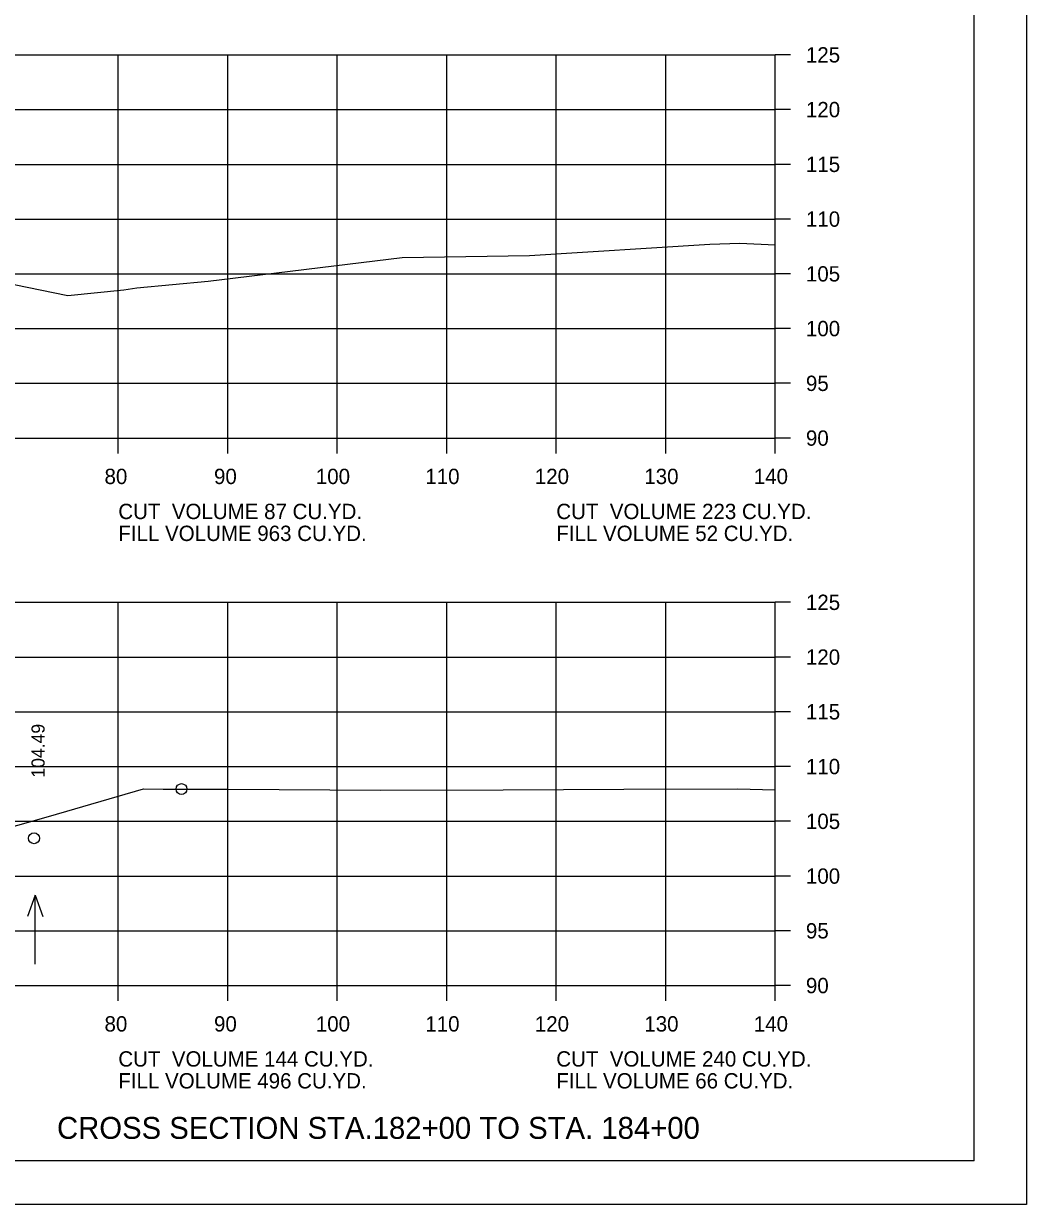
# Model space of a CAD drawing. Extents: x 1175611 to 1176402, y -433344 to -416213.
# Drawn here: x 1175852.3 to 1175943.9, y -426730.1 to -426622.2 of the extents above; entities that cross this region are included whole.
import ezdxf

# ---------------------------------------------------------------- set-up
doc = ezdxf.new("R2010")
doc.units = 0
for name, color, linetype in [('Default', 7, 'Continuous'), ('R_Axis', 7, 'Continuous'), ('R_Axis Annot', 7, 'Continuous'), ('R_Border', 7, 'Continuous'), ('R_Draft', 7, 'Continuous'), ('R_Exist Surface', 7, 'Continuous'), ('R_Grid', 7, 'Continuous'), ('R_No Plot', 7, 'Continuous'), ('R_Water Annot', 7, 'Continuous'), ('R_Xsect Elev', 7, 'Continuous')]:
    doc.layers.add(name, color=color, linetype=linetype)

msp = doc.modelspace()

# ---------------------------------------------------------------- linework, layer by layer
at = {"layer": 'R_Axis'}
for p, q in [((1175920.97, -426660.07), (1175920.97, -426625.07)), ((1175922.37, -426625.07), (1175920.97, -426625.07)), ((1175922.37, -426630.07), (1175920.97, -426630.07)), ((1175922.37, -426635.07), (1175920.97, -426635.07)), ((1175922.37, -426640.07), (1175920.97, -426640.07)), ((1175922.37, -426645.07), (1175920.97, -426645.07)), ((1175922.37, -426650.07), (1175920.97, -426650.07)), ((1175922.37, -426655.07), (1175920.97, -426655.07)), ((1175640.97, -426660.07), (1175920.97, -426660.07)), ((1175860.97, -426661.47), (1175860.97, -426660.07)), ((1175870.97, -426661.47), (1175870.97, -426660.07)), ((1175880.97, -426661.47), (1175880.97, -426660.07)), ((1175890.97, -426661.47), (1175890.97, -426660.07)), ((1175900.97, -426661.47), (1175900.97, -426660.07)), ((1175910.97, -426661.47), (1175910.97, -426660.07)), ((1175920.97, -426661.47), (1175920.97, -426660.07)), ((1175922.37, -426660.07), (1175920.97, -426660.07)), ((1175920.97, -426710.07), (1175920.97, -426675.07)), ((1175922.37, -426675.07), (1175920.97, -426675.07)), ((1175922.37, -426680.07), (1175920.97, -426680.07)), ((1175922.37, -426685.07), (1175920.97, -426685.07)), ((1175922.37, -426690.07), (1175920.97, -426690.07)), ((1175922.37, -426695.07), (1175920.97, -426695.07)), ((1175922.37, -426700.07), (1175920.97, -426700.07)), ((1175922.37, -426705.07), (1175920.97, -426705.07)), ((1175640.97, -426710.07), (1175920.97, -426710.07)), ((1175860.97, -426711.47), (1175860.97, -426710.07)), ((1175870.97, -426711.47), (1175870.97, -426710.07)), ((1175880.97, -426711.47), (1175880.97, -426710.07)), ((1175890.97, -426711.47), (1175890.97, -426710.07)), ((1175900.97, -426711.47), (1175900.97, -426710.07)), ((1175910.97, -426711.47), (1175910.97, -426710.07)), ((1175920.97, -426711.47), (1175920.97, -426710.07)), ((1175922.37, -426710.07), (1175920.97, -426710.07))]:
    msp.add_line(p, q, dxfattribs=at)
at = {"layer": 'R_Border'}
for q in [(1175939.15, -426520.61), (1175622.97, -426726.07)]:
    msp.add_line((1175939.15, -426726.07), q, dxfattribs=at)
at = {"layer": 'R_Exist Surface'}
for points in [[(1175846.69, -426645.08), (1175856.36, -426647.06), (1175861.47, -426646.53), (1175862.65, -426646.35), (1175869.17, -426645.75), (1175886.88, -426643.57), (1175898.51, -426643.4), (1175915, -426642.36), (1175917.73, -426642.28), (1175920.97, -426642.42)], [(1175850.39, -426695.82), (1175854.58, -426694.63), (1175863.27, -426692.09), (1175865.08, -426692.13), (1175870.99, -426692.14), (1175884.95, -426692.24), (1175896.13, -426692.19), (1175907.13, -426692.13), (1175917.52, -426692.11), (1175920.97, -426692.21)]]:
    msp.add_lwpolyline(points, dxfattribs=at)
at = {"layer": 'R_Grid'}
for p, q in [((1175640.97, -426625.07), (1175920.97, -426625.07)), ((1175860.97, -426660.07), (1175860.97, -426625.07)), ((1175870.97, -426660.07), (1175870.97, -426625.07)), ((1175880.97, -426660.07), (1175880.97, -426625.07)), ((1175890.97, -426660.07), (1175890.97, -426625.07)), ((1175900.97, -426660.07), (1175900.97, -426625.07)), ((1175910.97, -426660.07), (1175910.97, -426625.07)), ((1175920.97, -426660.07), (1175920.97, -426625.07)), ((1175640.97, -426630.07), (1175920.97, -426630.07)), ((1175640.97, -426635.07), (1175920.97, -426635.07)), ((1175640.97, -426640.07), (1175920.97, -426640.07)), ((1175640.97, -426645.07), (1175920.97, -426645.07)), ((1175640.97, -426650.07), (1175920.97, -426650.07)), ((1175640.97, -426655.07), (1175920.97, -426655.07)), ((1175640.97, -426660.07), (1175920.97, -426660.07)), ((1175640.97, -426675.07), (1175920.97, -426675.07)), ((1175860.97, -426710.07), (1175860.97, -426675.07)), ((1175870.97, -426710.07), (1175870.97, -426675.07)), ((1175880.97, -426710.07), (1175880.97, -426675.07)), ((1175890.97, -426710.07), (1175890.97, -426675.07)), ((1175900.97, -426710.07), (1175900.97, -426675.07)), ((1175910.97, -426710.07), (1175910.97, -426675.07)), ((1175920.97, -426710.07), (1175920.97, -426675.07)), ((1175640.97, -426680.07), (1175920.97, -426680.07)), ((1175640.97, -426685.07), (1175920.97, -426685.07)), ((1175640.97, -426690.07), (1175920.97, -426690.07)), ((1175640.97, -426695.07), (1175920.97, -426695.07)), ((1175640.97, -426700.07), (1175920.97, -426700.07)), ((1175640.97, -426705.07), (1175920.97, -426705.07)), ((1175640.97, -426710.07), (1175920.97, -426710.07))]:
    msp.add_line(p, q, dxfattribs=at)
at = {"layer": 'R_No Plot'}
msp.add_line((1175610.57, -426730.05), (1175943.91, -426730.05), dxfattribs=at)
msp.add_lwpolyline([(1175610.57, -426516.72), (1175943.91, -426516.72), (1175943.91, -426730.06), (1175610.57, -426730.06)], close=True, dxfattribs=at)
for centre in [(1175866.74, -426692.13), (1175853.27, -426696.62)]:
    msp.add_circle(centre, 0.5, dxfattribs=at)
at = {"layer": 'R_Water Annot'}
for p, q in [((1175853.37, -426701.82), (1175852.67, -426703.75)), ((1175853.37, -426708.11), (1175853.37, -426701.82)), ((1175853.37, -426701.82), (1175854.07, -426703.75))]:
    msp.add_line(p, q, dxfattribs=at)

# ---------------------------------------------------------------- texts
at = {"layer": 'Default'}
for s, p in [('CUT  VOLUME 87 CU.YD.', (1175860.97, -426667.47)), ('CUT  VOLUME 223 CU.YD.', (1175900.97, -426667.47)), ('FILL VOLUME 963 CU.YD.', (1175860.97, -426669.47)), ('FILL VOLUME 52 CU.YD.', (1175900.97, -426669.47)), ('CUT  VOLUME 144 CU.YD.', (1175860.97, -426717.47)), ('CUT  VOLUME 240 CU.YD.', (1175900.97, -426717.47)), ('FILL VOLUME 496 CU.YD.', (1175860.97, -426719.47)), ('FILL VOLUME 66 CU.YD.', (1175900.97, -426719.47))]:
    msp.add_text(s, height=1.4, dxfattribs=at).set_placement(p)
at = {"layer": 'R_Axis Annot'}
for s, p in [('125', (1175923.77, -426625.77)), ('120', (1175923.77, -426630.77)), ('115', (1175923.77, -426635.77)), ('110', (1175923.77, -426640.77)), ('105', (1175923.77, -426645.77)), ('100', (1175923.77, -426650.77)), ('95', (1175923.77, -426655.77)), ('90', (1175923.77, -426660.77)), ('80', (1175859.71, -426664.27)), ('90', (1175869.71, -426664.27)), ('100', (1175879.01, -426664.27)), ('110', (1175889.01, -426664.27)), ('120', (1175899.01, -426664.27)), ('130', (1175909.01, -426664.27)), ('140', (1175919.01, -426664.27)), ('125', (1175923.77, -426675.77)), ('120', (1175923.77, -426680.77)), ('115', (1175923.77, -426685.77)), ('110', (1175923.77, -426690.77)), ('105', (1175923.77, -426695.77)), ('100', (1175923.77, -426700.77)), ('95', (1175923.77, -426705.77)), ('90', (1175923.77, -426710.77)), ('80', (1175859.71, -426714.27)), ('90', (1175869.71, -426714.27)), ('100', (1175879.01, -426714.27)), ('110', (1175889.01, -426714.27)), ('120', (1175899.01, -426714.27)), ('130', (1175909.01, -426714.27)), ('140', (1175919.01, -426714.27))]:
    msp.add_text(s, height=1.4, dxfattribs=at).set_placement(p)
at = {"layer": 'R_Draft'}
msp.add_text('CROSS SECTION STA.182+00 TO STA. 184+00', height=2, dxfattribs=at).set_placement((1175855.37, -426724.07))
at = {"layer": 'R_Xsect Elev'}
msp.add_text('104.49', height=1.2, rotation=90, dxfattribs=at).set_placement((1175854.24, -426691.08))

doc.saveas('drawing.dxf')
